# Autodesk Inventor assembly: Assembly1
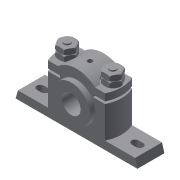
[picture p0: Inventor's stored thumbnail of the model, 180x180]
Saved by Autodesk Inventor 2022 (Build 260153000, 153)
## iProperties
Created: 2016-03
Part Number: Assembly1
Document SubType Name: Assembly
Designer: Sandeep
Author: Sandeep
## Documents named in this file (7)
- D:\PROJECTS_2021\Resources\Tutorial Files\c13_Inv_2022_tut\c13_Inv_tut_2022\c13-tut01-inv\Plummer block\Assembly1.iam
- D:\PROJECTS_2021\Resources\Tutorial Files\c13_Inv_2022_tut\c13_Inv_tut_2022\c13-tut01-inv\Plummer block\Casting.ipt
- D:\PROJECTS_2021\Resources\Tutorial Files\c13_Inv_2022_tut\c13_Inv_tut_2022\c13-tut01-inv\Plummer block\Brasses.ipt
- D:\PROJECTS_2021\Resources\Tutorial Files\c13_Inv_2022_tut\c13_Inv_tut_2022\c13-tut01-inv\Plummer block\Cap.ipt
- D:\PROJECTS_2021\Resources\Tutorial Files\c13_Inv_2022_tut\c13_Inv_tut_2022\c13-tut01-inv\Plummer block\Bolt.ipt
- D:\PROJECTS_2021\Resources\Tutorial Files\c13_Inv_2022_tut\c13_Inv_tut_2022\c13-tut01-inv\Plummer block\Nut.ipt
- D:\PROJECTS_2021\Resources\Tutorial Files\c13_Inv_2022_tut\c13_Inv_tut_2022\c13-tut01-inv\Plummer block\Lock Nut.ipt
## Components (9 placed, 6 different names)
1. Casting:1 — Mate:1, Mate:2, Insert:1, Insert:2, Angle:1, Angle:2
2. Brasses:1 — Mate:1, Mate:2, Mate:3, Mate:4
3. Cap:1 — Mate:3, Mate:4, Insert:3, Insert:5
4. Bolt:1 — Insert:1, Angle:1
5. Bolt:2 — Insert:2, Angle:2
6. Nut:1 — Insert:3, Insert:4
7. Nut:2 — Insert:5, Insert:6
8. Lock Nut:1 — Insert:4
9. Lock Nut:2 — Insert:6
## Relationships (12: Insert 6, Mate 4, Angle 2)
- Mate:1: Casting:1 ↔ Brasses:1
- Mate:2: Casting:1 ↔ Brasses:1
- Mate:3: Brasses:1 ↔ Cap:1
- Mate:4: Brasses:1 ↔ Cap:1
- Insert:1: Casting:1 ↔ Bolt:1
- Insert:2: Casting:1 ↔ Bolt:2
- Angle:1: Casting:1 ↔ Bolt:1
- Angle:2: Casting:1 ↔ Bolt:2
- Insert:3: Cap:1 ↔ Nut:1
- Insert:4: Nut:1 ↔ Lock Nut:1
- Insert:5: Cap:1 ↔ Nut:2
- Insert:6: Nut:2 ↔ Lock Nut:2
